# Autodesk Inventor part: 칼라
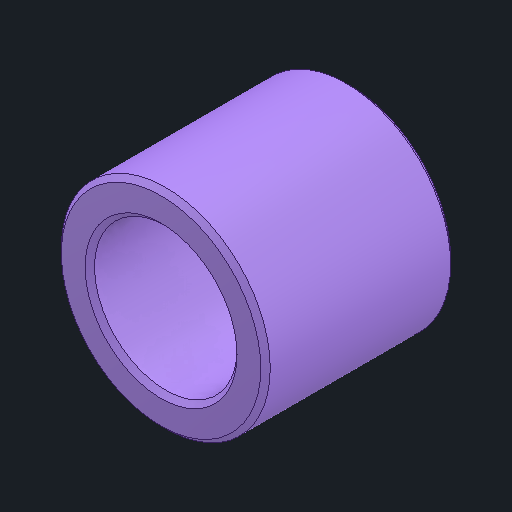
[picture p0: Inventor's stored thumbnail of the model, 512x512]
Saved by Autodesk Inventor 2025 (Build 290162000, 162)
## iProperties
Created: 2025-08
Part Number: 칼라
Material: 스테인리스강
Document SubType Name: Modeling
Designer: infra006
Density: 8.08 g/cm^3
Appearance: 기본값
Author: jhkim
Sending System: Autodesk Inventor 2026
Preprocessor: ST-DEVELOPER v20.1
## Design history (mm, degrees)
feature "솔리드1"
node "솔리드2"
